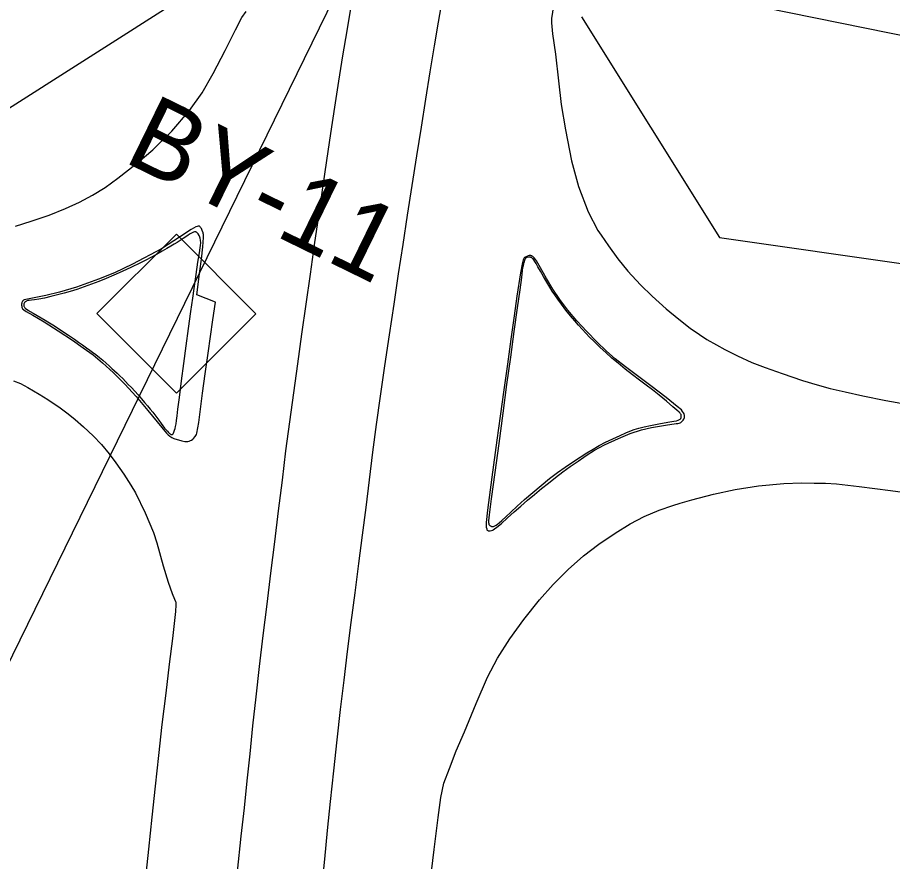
# Model space of a CAD drawing. Extents: x 1517485 to 1521905, y 636528 to 640355.
# Drawn here: x 1520407.4 to 1520638.4, y 638277.1 to 638499.8 of the extents above; entities that cross this region are included whole.
import ezdxf

# ---------------------------------------------------------------- set-up
doc = ezdxf.new("R2010")
doc.units = 0
for name, color, linetype in [('CTL Secondary Horizontal and Vertical CELL', 7, 'Continuous'), ('CTL Secondary Horizontal and Vertical Text', 7, 'Continuous'), ('Exist Building', 7, 'Continuous'), ('Exist Right of Way Line', 7, 'Continuous'), ('Exist Roads Curbs', 7, 'Continuous'), ('Exist Roads EOP', 7, 'Continuous'), ('Scratch_Level_3', 7, 'Continuous')]:
    doc.layers.add(name, color=color, linetype=linetype)

msp = doc.modelspace()

# ---------------------------------------------------------------- linework, layer by layer
at = {"layer": 'CTL Secondary Horizontal and Vertical CELL'}
msp.add_line((1520449.2, 638421.6), (1520449.2, 638421.6), dxfattribs=at)
msp.add_lwpolyline([(1520428.34, 638421.67), (1520449.31, 638442.64), (1520470.31, 638421.64), (1520449.35, 638400.67)], close=True, dxfattribs=at)
at = {"layer": 'Exist Building'}
msp.add_lwpolyline([(1520578.55, 638507.74), (1520628.44, 638753.1), (1520785.56, 638721.15), (1520735.68, 638475.79)], close=True, dxfattribs=at)
at = {"layer": 'Exist Right of Way Line'}
for p, q in [((1520397.94, 638471.31), (1520456.28, 638508.46)), ((1520556.23, 638499.97), (1520592.71, 638441.73)), ((1520592.71, 638441.73), (1520859.18, 638403.68))]:
    msp.add_line(p, q, dxfattribs=at)
at = {"layer": 'Exist Roads Curbs'}
for points in [[(1520453.63, 638425.7), (1520454, 638428.31), (1520454.53, 638431.95), (1520455.02, 638435.25), (1520455.39, 638437.75), (1520455.61, 638438.99), (1520455.7, 638439.62), (1520455.73, 638440.33), (1520455.69, 638441.01), (1520455.59, 638441.6), (1520455.42, 638442.1), (1520455.32, 638442.32), (1520455.06, 638442.69), (1520454.82, 638442.96), (1520454.71, 638443.06), (1520454.6, 638443.14), (1520454.5, 638443.2), (1520454.41, 638443.25), (1520454.33, 638443.27), (1520454.24, 638443.27), (1520454.12, 638443.25), (1520453.83, 638443.15), (1520453.46, 638442.98), (1520453, 638442.71), (1520452.46, 638442.37), (1520451.83, 638441.94), (1520451.12, 638441.46), (1520450.33, 638440.94), (1520449.51, 638440.43), (1520448.71, 638439.96), (1520447.83, 638439.45), (1520446.78, 638438.83), (1520445.53, 638438.11), (1520444.06, 638437.29), (1520442.57, 638436.47), (1520441.25, 638435.76), (1520439.67, 638434.97), (1520437.43, 638433.89), (1520434.99, 638432.76), (1520432.79, 638431.79), (1520430.77, 638430.94), (1520428.85, 638430.18), (1520426.94, 638429.46), (1520424.94, 638428.73), (1520423.01, 638428.06), (1520421.31, 638427.54), (1520419.68, 638427.07), (1520417.94, 638426.6), (1520416.17, 638426.15), (1520414.47, 638425.78), (1520412.98, 638425.5), (1520411.88, 638425.33), (1520411.07, 638425.23), (1520410.5, 638425.16), (1520410.11, 638425.1), (1520409.87, 638425.04), (1520409.71, 638424.97), (1520409.56, 638424.89), (1520409.42, 638424.79), (1520409.29, 638424.68), (1520409.24, 638424.62), (1520409.19, 638424.55), (1520409.15, 638424.48), (1520409.11, 638424.39), (1520409.06, 638424.21), (1520409.04, 638424.01), (1520409.04, 638423.9), (1520409.05, 638423.78), (1520409.08, 638423.66), (1520409.12, 638423.53), (1520409.19, 638423.4), (1520409.28, 638423.27), (1520409.41, 638423.14), (1520409.73, 638422.87), (1520410.17, 638422.57), (1520410.74, 638422.23), (1520411.55, 638421.75), (1520412.58, 638421.15), (1520413.63, 638420.53), (1520414.68, 638419.91), (1520415.82, 638419.23), (1520417.11, 638418.43), (1520418.82, 638417.33), (1520420.85, 638415.99), (1520422.43, 638414.92), (1520423.51, 638414.14), (1520424.53, 638413.41), (1520425.55, 638412.67), (1520426.44, 638412.03), (1520427.2, 638411.48), (1520428.05, 638410.84), (1520428.98, 638410.11), (1520429.89, 638409.36), (1520430.75, 638408.6), (1520431.55, 638407.88), (1520432.29, 638407.21), (1520432.99, 638406.57), (1520433.67, 638405.94), (1520434.39, 638405.25), (1520435.15, 638404.5), (1520435.9, 638403.75), (1520436.63, 638402.99), (1520437.44, 638402.14), (1520438.33, 638401.2), (1520439.23, 638400.21), (1520440.11, 638399.19), (1520440.93, 638398.23), (1520441.69, 638397.33), (1520442.41, 638396.47), (1520443.1, 638395.62), (1520443.86, 638394.63), (1520444.66, 638393.53), (1520445.3, 638392.65), (1520445.78, 638392.01), (1520446.21, 638391.47), (1520446.61, 638391), (1520446.96, 638390.62), (1520447.25, 638390.32), (1520447.49, 638390.07), (1520447.7, 638389.9), (1520447.79, 638389.83), (1520447.88, 638389.78), (1520447.95, 638389.75), (1520448.03, 638389.74), (1520448.1, 638389.74), (1520448.18, 638389.76), (1520448.25, 638389.79), (1520448.32, 638389.84), (1520448.39, 638389.89), (1520448.44, 638389.95), (1520448.49, 638390.01), (1520448.54, 638390.1), (1520448.67, 638390.41), (1520448.82, 638390.87), (1520448.97, 638391.35), (1520449.1, 638391.86), (1520449.22, 638392.54), (1520449.34, 638393.45), (1520449.5, 638394.7), (1520449.72, 638396.45), (1520450.11, 638399.55), (1520450.68, 638403.94), (1520451.3, 638408.54), (1520451.94, 638413.15), (1520452.56, 638417.72), (1520453.14, 638422.19)], [(1520539.97, 638427.97), (1520539.32, 638423.18), (1520538.44, 638416.95), (1520537.49, 638410.17), (1520536.5, 638402.99), (1520535.47, 638395.37), (1520534.41, 638387.41), (1520533.38, 638379.74), (1520532.44, 638372.78), (1520531.89, 638368.53), (1520531.75, 638367), (1520531.75, 638366.56), (1520531.78, 638366.25), (1520531.84, 638366.04), (1520531.93, 638365.91), (1520532.03, 638365.79), (1520532.14, 638365.7), (1520532.26, 638365.62), (1520532.39, 638365.56), (1520532.53, 638365.52), (1520532.68, 638365.5), (1520532.84, 638365.5), (1520533, 638365.52), (1520533.17, 638365.57), (1520533.34, 638365.63), (1520533.71, 638365.83), (1520534.09, 638366.09), (1520534.53, 638366.45), (1520535.24, 638367.07), (1520536.26, 638368), (1520537.62, 638369.28), (1520539.3, 638370.89), (1520541.23, 638372.64), (1520543.38, 638374.5), (1520545.6, 638376.33), (1520547.84, 638378.11), (1520549.96, 638379.7), (1520551.94, 638381.11), (1520553.91, 638382.46), (1520555.88, 638383.77), (1520557.68, 638384.93), (1520559.31, 638385.92), (1520560.95, 638386.83), (1520562.64, 638387.7), (1520564.5, 638388.61), (1520566.45, 638389.53), (1520567.97, 638390.22), (1520569.05, 638390.66), (1520570.15, 638391.04), (1520571.38, 638391.4), (1520572.82, 638391.78), (1520574.51, 638392.18), (1520576.64, 638392.61), (1520579.05, 638393.03), (1520580.64, 638393.3), (1520581.33, 638393.41), (1520581.8, 638393.55), (1520581.99, 638393.63), (1520582.15, 638393.72), (1520582.29, 638393.81), (1520582.39, 638393.9), (1520582.45, 638393.99), (1520582.5, 638394.08), (1520582.53, 638394.19), (1520582.56, 638394.31), (1520582.58, 638394.59), (1520582.57, 638394.84), (1520582.56, 638394.94), (1520582.53, 638395.05), (1520582.49, 638395.15), (1520582.43, 638395.26), (1520582.35, 638395.38), (1520582.04, 638395.7), (1520581.45, 638396.21), (1520580.39, 638397.09), (1520578.69, 638398.54), (1520576.76, 638400.15), (1520575.02, 638401.54), (1520573.35, 638402.82), (1520571.6, 638404.11), (1520569.76, 638405.48), (1520567.81, 638407.02), (1520565.93, 638408.55), (1520564.3, 638409.92), (1520562.76, 638411.3), (1520561.1, 638412.84), (1520559.57, 638414.31), (1520558.41, 638415.49), (1520557.43, 638416.52), (1520556.47, 638417.57), (1520555.5, 638418.65), (1520554.5, 638419.79), (1520553.4, 638421.07), (1520552.15, 638422.6), (1520550.94, 638424.14), (1520549.98, 638425.46), (1520549.21, 638426.58), (1520548.56, 638427.56), (1520547.9, 638428.62), (1520547.1, 638429.96), (1520546.25, 638431.43), (1520545.43, 638432.85), (1520544.74, 638434.05), (1520544.28, 638434.86), (1520543.95, 638435.4), (1520543.68, 638435.82), (1520543.46, 638436.11), (1520543.35, 638436.23), (1520543.26, 638436.32), (1520543.15, 638436.39), (1520543.04, 638436.44), (1520542.92, 638436.49), (1520542.8, 638436.52), (1520542.65, 638436.53), (1520542.32, 638436.53), (1520541.94, 638436.47), (1520541.79, 638436.44), (1520541.67, 638436.4), (1520541.59, 638436.35), (1520541.52, 638436.29), (1520541.46, 638436.23), (1520541.41, 638436.15), (1520541.32, 638435.96), (1520541.21, 638435.69), (1520541.09, 638435.33), (1520540.96, 638434.86), (1520540.83, 638434.31), (1520540.73, 638433.76), (1520540.63, 638433.07), (1520540.39, 638431.21)]]:
    msp.add_lwpolyline(points, close=True, dxfattribs=at)
at = {"layer": 'Exist Roads EOP'}
for points in [[(1520487.71, 638269.93), (1520488.48, 638277.66), (1520489.22, 638285.24), (1520490, 638292.92), (1520490.84, 638301), (1520491.73, 638309.18), (1520492.65, 638317.15), (1520493.58, 638324.94), (1520494.53, 638332.53), (1520495.49, 638340.13), (1520496.48, 638347.94), (1520497.47, 638355.71), (1520498.45, 638363.19), (1520499.38, 638370.52), (1520500.28, 638377.83), (1520501.18, 638385.12), (1520502.13, 638392.39), (1520503.17, 638399.89), (1520504.34, 638407.88), (1520505.57, 638416.06), (1520506.78, 638424.17), (1520507.98, 638432.14), (1520509.16, 638439.93), (1520510.36, 638447.66), (1520511.57, 638455.5), (1520512.79, 638463.27), (1520514, 638470.84), (1520515.18, 638478.23), (1520516.34, 638485.48), (1520517.44, 638492.34), (1520518.48, 638498.57), (1520519.64, 638505.27)], [(1520495.41, 638502.68), (1520494.3, 638496.26), (1520493.21, 638489.71), (1520492.13, 638483.02), (1520491.07, 638476.18), (1520490.02, 638469.17), (1520488.96, 638462.06), (1520487.88, 638454.84), (1520486.8, 638447.44), (1520485.71, 638439.83), (1520484.61, 638432.06), (1520483.5, 638424.14), (1520482.39, 638416.24), (1520481.3, 638408.41), (1520480.22, 638400.72), (1520479.15, 638393.14), (1520478.15, 638385.48), (1520477.2, 638377.69), (1520476.22, 638369.66), (1520475.19, 638361.42), (1520474.17, 638353.19), (1520473.17, 638345), (1520472.17, 638336.76), (1520471.18, 638328.52), (1520470.27, 638320.53), (1520469.45, 638312.85), (1520468.68, 638305.46), (1520467.94, 638298.33), (1520467.18, 638291.21), (1520466.35, 638283.78), (1520465.34, 638274.48)], [(1520548.84, 638502.85), (1520548.34, 638499.52), (1520548.3, 638498.41), (1520548.61, 638495.54), (1520549.39, 638490.13), (1520550.23, 638483.09), (1520550.93, 638476.81), (1520552, 638470.17), (1520553.6, 638462.02), (1520555.45, 638455.22), (1520557.98, 638448.49), (1520560.53, 638443.62), (1520561.43, 638442.33), (1520563.4, 638439.55), (1520565.87, 638436.1), (1520568.48, 638432.86), (1520571.8, 638429.24), (1520574.88, 638426.23), (1520578.59, 638422.95), (1520581.94, 638420.17), (1520584.94, 638417.87), (1520587.39, 638416.15), (1520589.39, 638414.87), (1520591.88, 638413.42), (1520594.1, 638412.21), (1520597.42, 638410.51), (1520601.26, 638408.78), (1520604.73, 638407.46), (1520609.27, 638405.86), (1520614.59, 638404.04), (1520618.45, 638402.83), (1520621.87, 638401.93), (1520625.87, 638400.98), (1520630.49, 638399.93), (1520636.62, 638398.74), (1520642.07, 638397.79)], [(1520406.83, 638444.75), (1520411.02, 638446.04), (1520415.7, 638447.65), (1520420.07, 638449.4), (1520423.7, 638451.09), (1520427.16, 638452.92), (1520430.51, 638454.98), (1520433.83, 638457.39), (1520438.67, 638461.18), (1520443.12, 638464.86), (1520448.08, 638469.82), (1520452.77, 638475.23), (1520456.11, 638479.91), (1520459.07, 638485.07), (1520462.18, 638491.11), (1520464.91, 638496.53), (1520466.63, 638499.78), (1520467.7, 638501.42)], [(1520406.33, 638403.95), (1520408.16, 638403.18), (1520410.14, 638402.16), (1520413.1, 638400.43), (1520415.41, 638399), (1520418.62, 638396.77), (1520420.76, 638395.2), (1520422.64, 638393.7), (1520424.77, 638391.83), (1520427.37, 638389.39), (1520429.55, 638387.11), (1520431.56, 638384.68), (1520433.34, 638382.28), (1520435.42, 638379.26), (1520437.27, 638376.4), (1520438.49, 638374.35), (1520441.11, 638369.05), (1520443.27, 638363.92), (1520444.15, 638361.16), (1520445.85, 638355.13), (1520447.18, 638350.79), (1520448.22, 638347.8), (1520448.82, 638346.3), (1520449.12, 638345.66), (1520449.16, 638345.52), (1520449.19, 638345.38), (1520449.2, 638344.79), (1520449.08, 638343.09), (1520448.29, 638335.95), (1520447.44, 638329.19), (1520446.5, 638321.51), (1520445.5, 638313.22), (1520444.57, 638305.01), (1520443.7, 638296.95), (1520442.83, 638288.74), (1520441.94, 638280.37), (1520441.12, 638272.07)], [(1520516.69, 638274.43), (1520517.36, 638280.25), (1520518.4, 638288.71), (1520519.14, 638293.96), (1520519.96, 638297.72), (1520521.39, 638301.66), (1520523.22, 638306.3), (1520525.35, 638311.32), (1520528.46, 638318.79), (1520531.43, 638325.74), (1520534.12, 638330.76), (1520537.3, 638335.81), (1520541, 638340.92), (1520545.16, 638346.1), (1520548.8, 638350.22), (1520552.7, 638354.1), (1520556.81, 638357.75), (1520560.8, 638360.78), (1520565.16, 638363.75), (1520569.14, 638366.19), (1520572.84, 638368.11), (1520576.74, 638369.77), (1520580.34, 638371.03), (1520582.32, 638371.61), (1520585.4, 638372.48), (1520591.11, 638374.02), (1520596.85, 638375.29), (1520602.96, 638376.21), (1520609.64, 638376.82), (1520614.36, 638377.03), (1520617.66, 638376.96), (1520620.71, 638376.88), (1520623.56, 638376.71), (1520629.58, 638376.01), (1520637.85, 638374.95), (1520646.25, 638373.81)]]:
    msp.add_lwpolyline(points, dxfattribs=at)
for points in [[(1520454.69, 638426.64), (1520455.55, 638432.9), (1520455.99, 638436.02), (1520456.31, 638439.26), (1520456.46, 638441.79), (1520456.45, 638442.54), (1520456.42, 638442.8), (1520456.37, 638442.99), (1520456.13, 638443.64), (1520455.91, 638444.13), (1520455.72, 638444.43), (1520455.62, 638444.57), (1520455.53, 638444.66), (1520455.49, 638444.69), (1520455.44, 638444.71), (1520455.39, 638444.73), (1520455.34, 638444.75), (1520455.27, 638444.75), (1520455.07, 638444.73), (1520454.79, 638444.67), (1520454.47, 638444.56), (1520453.26, 638443.87), (1520450.41, 638441.98), (1520445.35, 638438.78), (1520437.76, 638434.69), (1520432.96, 638432.41), (1520428.76, 638430.73), (1520422.98, 638428.65), (1520418.44, 638427.3), (1520414.82, 638426.41), (1520411.74, 638425.79), (1520409.17, 638425.29), (1520408.99, 638425.21), (1520408.9, 638425.14), (1520408.81, 638425.06), (1520408.73, 638424.95), (1520408.59, 638424.71), (1520408.54, 638424.58), (1520408.5, 638424.46), (1520408.46, 638424.19), (1520408.46, 638423.92), (1520408.49, 638423.63), (1520408.54, 638423.37), (1520408.63, 638423.14), (1520408.68, 638423.03), (1520408.74, 638422.95), (1520409.04, 638422.64), (1520409.67, 638422.22), (1520411.41, 638421.26), (1520414.45, 638419.46), (1520418.11, 638417.16), (1520421.86, 638414.64), (1520424.73, 638412.65), (1520427.33, 638410.75), (1520429.83, 638408.71), (1520432.74, 638406.03), (1520435.67, 638403.09), (1520438.68, 638399.82), (1520441.82, 638396.14), (1520444.25, 638393.11), (1520446.68, 638390.14), (1520447.14, 638389.67), (1520447.59, 638389.29), (1520448.08, 638388.97), (1520448.62, 638388.7), (1520450.75, 638388.07), (1520451.55, 638387.92), (1520451.93, 638387.91), (1520452.3, 638387.94), (1520452.67, 638388.02), (1520453.02, 638388.14), (1520453.34, 638388.29), (1520453.63, 638388.49), (1520453.88, 638388.72), (1520454.31, 638389.23), (1520454.62, 638389.75), (1520454.75, 638390.09), (1520455.26, 638392.97), (1520456.25, 638400.63), (1520456.94, 638405.78), (1520457.7, 638411.27), (1520458.96, 638420.05), (1520459.61, 638424.66)], [(1520557.45, 638384.22), (1520559.65, 638385.61), (1520562.35, 638387), (1520566.04, 638388.75), (1520569.14, 638390.04), (1520572.07, 638391.01), (1520574.73, 638391.64), (1520578.42, 638392.24), (1520581.29, 638392.63), (1520581.67, 638392.68), (1520582.07, 638392.78), (1520582.28, 638392.85), (1520582.47, 638392.95), (1520582.64, 638393.07), (1520582.79, 638393.21), (1520583.06, 638393.52), (1520583.27, 638393.85), (1520583.35, 638394.02), (1520583.41, 638394.21), (1520583.44, 638394.41), (1520583.45, 638394.61), (1520583.44, 638394.83), (1520583.39, 638395.04), (1520583.32, 638395.25), (1520583.22, 638395.46), (1520582.95, 638395.86), (1520582.62, 638396.24), (1520581.55, 638397.15), (1520578.59, 638399.5), (1520574.56, 638402.65), (1520571.06, 638405.24), (1520567.9, 638407.58), (1520565.19, 638409.75), (1520562.85, 638411.8), (1520560.32, 638414.22), (1520557.63, 638416.93), (1520555.07, 638419.73), (1520552.61, 638422.6), (1520550.54, 638425.35), (1520548.72, 638428.13), (1520547.03, 638430.93), (1520545.43, 638433.71), (1520544.35, 638435.57), (1520543.87, 638436.26), (1520543.54, 638436.62), (1520543.38, 638436.76), (1520543.2, 638436.87), (1520543.11, 638436.92), (1520543.02, 638436.95), (1520542.92, 638436.97), (1520542.83, 638436.99), (1520542.73, 638436.99), (1520542.48, 638436.96), (1520542.16, 638436.89), (1520541.79, 638436.77), (1520541.39, 638436.59), (1520541.23, 638436.48), (1520541.11, 638436.36), (1520541.01, 638436.22), (1520540.86, 638435.87), (1520540.56, 638434.76), (1520540.14, 638432.46), (1520539.23, 638426.3), (1520538.48, 638421.08), (1520537.6, 638414.9), (1520536.71, 638408.34), (1520535.78, 638401.52), (1520534.82, 638394.6), (1520533.93, 638388.23), (1520532.59, 638378.47), (1520531.43, 638369.8), (1520531.07, 638366.51), (1520531.06, 638365.79), (1520531.12, 638365.29), (1520531.23, 638364.84), (1520531.31, 638364.64), (1520531.4, 638364.49), (1520531.51, 638364.39), (1520531.62, 638364.32), (1520531.76, 638364.3), (1520531.92, 638364.3), (1520532.11, 638364.33), (1520532.54, 638364.44), (1520532.84, 638364.56), (1520532.93, 638364.61), (1520533.31, 638364.87), (1520533.94, 638365.29), (1520535.12, 638366.28), (1520536.77, 638367.79), (1520538.46, 638369.32), (1520540.21, 638370.86), (1520542, 638372.41), (1520543.82, 638373.95), (1520545.66, 638375.47), (1520547.53, 638376.96), (1520549.4, 638378.42), (1520551.32, 638379.87), (1520553.31, 638381.32), (1520555.35, 638382.77)]]:
    msp.add_lwpolyline(points, close=True, dxfattribs=at)
at = {"layer": 'Scratch_Level_3'}
msp.add_line((1520770.84, 639077.45), (1520017.02, 637536.16), dxfattribs=at)

# ---------------------------------------------------------------- texts
at = {"layer": 'CTL Secondary Horizontal and Vertical Text'}
msp.add_text('BY-11', height=20, rotation=333.9377, dxfattribs=at).set_placement((1520434.94, 638461.97))

doc.saveas('drawing.dxf')
